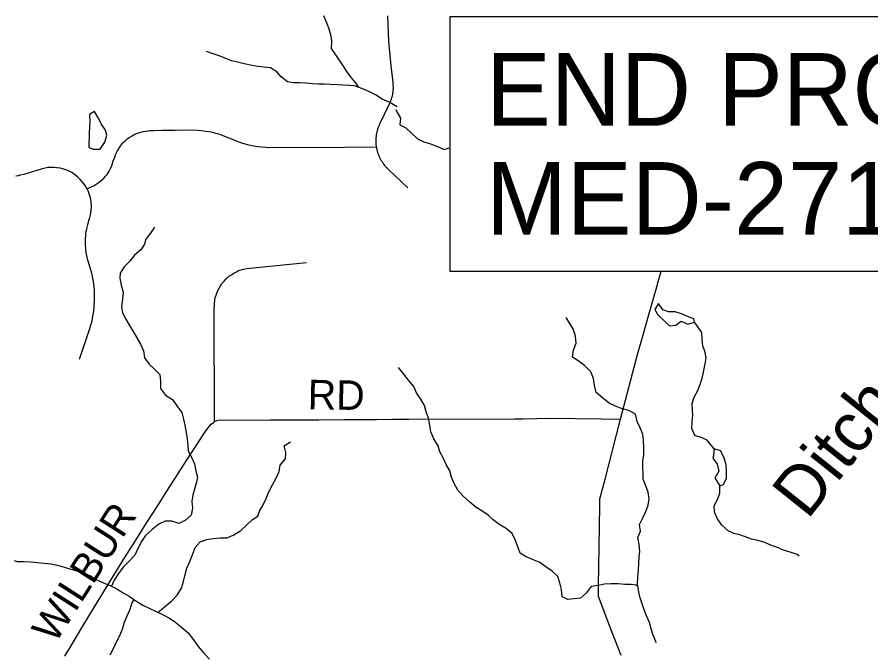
# Model space of a CAD drawing. Extents: x 0 to 34, y 0 to 22.
# Drawn here: x 5.327 to 6.974, y 16.805 to 18.033 of the extents above; entities that cross this region are included whole.
import ezdxf

# ---------------------------------------------------------------- set-up
doc = ezdxf.new("R2010")
doc.units = 0
for name, color, linetype in [('GM_X_County_Road', 7, 'Continuous'), ('GM_X_Minor_Lake', 7, 'Continuous'), ('GM_X_Minor_River', 7, 'Continuous'), ('GM_X_Minor_River_Text', 7, 'Continuous'), ('GM_X_Township_Road', 7, 'Continuous'), ('GM_X_Township_Road_Text', 7, 'Continuous'), ('SH_Text', 7, 'Continuous')]:
    doc.layers.add(name, color=color, linetype=linetype)

msp = doc.modelspace()

# ---------------------------------------------------------------- linework, layer by layer
at = {"layer": 'GM_X_County_Road'}
msp.add_lwpolyline([(6.4919, 16.8022), (6.4736, 16.8498), (6.448, 16.9162), (6.4482, 16.925), (6.4483, 16.9364), (6.4495, 17.0108), (6.4507, 17.0905), (6.451, 17.1044), (6.4603, 17.1399), (6.4907, 17.2575), (6.5234, 17.3825), (6.5342, 17.4204), (6.5433, 17.4522), (6.5524, 17.4842), (6.5619, 17.5175), (6.5622, 17.5188), (6.5692, 17.5433)], dxfattribs=at)
at = {"layer": 'GM_X_Minor_Lake'}
for points in [[(5.4854, 17.8353), (5.4831, 17.84), (5.4763, 17.8511), (5.4667, 17.8453), (5.4675, 17.8324), (5.4668, 17.8203), (5.466, 17.8088), (5.4653, 17.7815), (5.4742, 17.7784)], [(5.4854, 17.8353), (5.4831, 17.84), (5.4763, 17.8511), (5.4667, 17.8453), (5.4675, 17.8324), (5.4668, 17.8203), (5.466, 17.8088), (5.4653, 17.7815), (5.4741, 17.7785)], [(6.0573, 17.8544), (6.0592, 17.8503), (6.0664, 17.8377), (6.0653, 17.8252), (6.0767, 17.8191), (6.087, 17.81), (6.0992, 17.7978), (6.1114, 17.7925), (6.1243, 17.7884), (6.1377, 17.7831), (6.1506, 17.7774), (6.1601, 17.7808)], [(6.0573, 17.8544), (6.0592, 17.8503), (6.0664, 17.8377), (6.0653, 17.8252), (6.0767, 17.8191), (6.087, 17.81), (6.0992, 17.7978), (6.1114, 17.7925), (6.1243, 17.7884), (6.1377, 17.7831), (6.1506, 17.7774), (6.1601, 17.7808)], [(5.4741, 17.7784), (5.4874, 17.7781), (5.4965, 17.7918), (5.5003, 17.8055), (5.4976, 17.815), (5.4892, 17.8271), (5.4854, 17.8352)], [(5.4742, 17.7784), (5.4874, 17.7781), (5.4965, 17.7918), (5.5003, 17.8055), (5.4976, 17.815), (5.4892, 17.8271), (5.4854, 17.8353)], [(6.6332, 17.4445), (6.632, 17.4514), (6.6221, 17.4548), (6.6084, 17.4608), (6.5962, 17.465), (6.5833, 17.4646), (6.5723, 17.4684), (6.5639, 17.4806), (6.5567, 17.4691)], [(6.6332, 17.4445), (6.632, 17.4514), (6.6221, 17.4548), (6.6084, 17.4608), (6.5962, 17.465), (6.5833, 17.4646), (6.5723, 17.4684), (6.5639, 17.4806), (6.5567, 17.4691)], [(6.5567, 17.4691), (6.5628, 17.4589), (6.5742, 17.4482), (6.5849, 17.4376), (6.5974, 17.4388), (6.6077, 17.4464), (6.6202, 17.4411), (6.6332, 17.4445)], [(6.5567, 17.4691), (6.5628, 17.4589), (6.5742, 17.4482), (6.5849, 17.4376), (6.5974, 17.4388), (6.6077, 17.4464), (6.6202, 17.4411), (6.6332, 17.4445)], [(6.6819, 17.129), (6.6892, 17.132), (6.6953, 17.1442), (6.6952, 17.1579), (6.6945, 17.17), (6.6903, 17.1834), (6.6838, 17.197), (6.6716, 17.2004), (6.6701, 17.1871)], [(6.682, 17.129), (6.6892, 17.132), (6.6953, 17.1442), (6.6952, 17.1579), (6.6945, 17.17), (6.6903, 17.1834), (6.6838, 17.197), (6.6716, 17.2004), (6.6701, 17.1871)], [(6.6701, 17.1871), (6.669, 17.1826), (6.6773, 17.1708), (6.68, 17.1579), (6.6724, 17.1442), (6.6819, 17.129)], [(6.6701, 17.1871), (6.669, 17.1826), (6.6773, 17.1708), (6.68, 17.1579), (6.6724, 17.1442), (6.6819, 17.129)]]:
    msp.add_lwpolyline(points, dxfattribs=at)
at = {"layer": 'GM_X_Minor_River'}
for points in [[(5.9863, 17.8972), (5.9822, 17.9038), (5.9719, 17.9159), (5.9632, 17.9281), (5.9555, 17.9399), (5.9471, 17.9524), (5.9403, 17.9619), (5.9334, 17.9722), (5.9342, 17.9862), (5.933, 17.9961), (5.9288, 18.0098), (5.9242, 18.022), (5.9185, 18.0349)], [(6.0603, 17.8597), (6.0443, 17.8685), (6.0314, 17.8746), (6.0184, 17.8829), (6.0055, 17.8894), (5.9918, 17.8954), (5.978, 17.9), (5.9685, 17.9007), (5.9556, 17.9018), (5.9434, 17.9022), (5.9309, 17.9026), (5.9194, 17.9037), (5.9092, 17.9033), (5.8962, 17.9041), (5.8844, 17.9056), (5.8719, 17.9059), (5.8601, 17.9063), (5.8487, 17.9082), (5.8365, 17.9177), (5.8281, 17.9272), (5.8159, 17.9347), (5.8033, 17.9363), (5.7912, 17.9374), (5.7775, 17.94), (5.7649, 17.9427), (5.752, 17.9461), (5.7405, 17.9483), (5.7284, 17.9536), (5.7147, 17.9586), (5.7051, 17.962), (5.6926, 17.9662)], [(5.5923, 17.628), (5.5843, 17.6162), (5.5756, 17.6048), (5.5725, 17.5953), (5.5657, 17.5839), (5.5535, 17.574), (5.5448, 17.5626), (5.5338, 17.5511), (5.5262, 17.539), (5.5254, 17.5295), (5.5277, 17.5162), (5.532, 17.5029), (5.5304, 17.4892), (5.5282, 17.4755), (5.5305, 17.4629), (5.537, 17.4508), (5.5442, 17.4382), (5.5511, 17.4265), (5.5583, 17.4147), (5.5652, 17.4025), (5.5709, 17.3896), (5.5729, 17.3763), (5.5816, 17.3638), (5.5923, 17.3539), (5.6026, 17.3436), (5.6034, 17.3307), (5.6034, 17.317), (5.6133, 17.3041), (5.627, 17.2954), (5.6354, 17.2832), (5.6449, 17.2707), (5.648, 17.2581), (5.6503, 17.246), (5.653, 17.2323), (5.6553, 17.2194), (5.6561, 17.2064), (5.6568, 17.1969), (5.6633, 17.1844), (5.6694, 17.1715), (5.6717, 17.1585), (5.6748, 17.146), (5.6733, 17.1365), (5.6695, 17.1232), (5.6657, 17.1114), (5.6638, 17.0992), (5.6654, 17.0863), (5.6627, 17.073), (5.6517, 17.0631), (5.6395, 17.0566), (5.6254, 17.0611), (5.6125, 17.0615), (5.6003, 17.0554), (5.5874, 17.0451), (5.5749, 17.0337), (5.5669, 17.0223), (5.5608, 17.0097), (5.554, 16.996), (5.5441, 16.985), (5.532, 16.9724), (5.5229, 16.9602), (5.5145, 16.9477), (5.5091, 16.9359)], [(6.5596, 16.8267), (6.5587, 16.8292), (6.5534, 16.8417), (6.5496, 16.8535), (6.5465, 16.866), (6.5408, 16.879), (6.5362, 16.8904), (6.5324, 16.9018), (6.5282, 16.9151), (6.5251, 16.928), (6.5232, 16.9405), (6.5239, 16.9535), (6.5254, 16.9668), (6.5258, 16.9797), (6.5265, 16.993), (6.5277, 17.0025), (6.5269, 17.0162), (6.5238, 17.0295), (6.5295, 17.0417), (6.5272, 17.0546), (6.534, 17.0676), (6.5397, 17.0801), (6.5443, 17.0919), (6.5462, 17.1045), (6.5442, 17.1174), (6.5393, 17.1292), (6.5347, 17.1421), (6.5343, 17.152), (6.5339, 17.1645), (6.5339, 17.1767), (6.5354, 17.1896), (6.5354, 17.2029), (6.535, 17.2162), (6.5338, 17.2288), (6.5285, 17.241), (6.5227, 17.2535), (6.5197, 17.2672), (6.5067, 17.2744), (6.4942, 17.2778), (6.4808, 17.2831), (6.4687, 17.2888), (6.4568, 17.2983), (6.4439, 17.3093), (6.4404, 17.3226), (6.4389, 17.3363), (6.4332, 17.3488), (6.421, 17.361), (6.4092, 17.3701), (6.3978, 17.3773), (6.4, 17.3906), (6.4049, 17.4043), (6.4042, 17.418), (6.4, 17.4305), (6.386, 17.4535)], [(6.6715, 17.2004), (6.6579, 17.2175), (6.6464, 17.2225), (6.6343, 17.2266), (6.6282, 17.2396), (6.6289, 17.2525), (6.63, 17.2654), (6.6296, 17.2749), (6.6288, 17.2882), (6.6326, 17.3004), (6.6395, 17.313), (6.6448, 17.3267), (6.6486, 17.3396), (6.6516, 17.3518), (6.6538, 17.3643), (6.6557, 17.3761), (6.6534, 17.389), (6.6492, 17.3985), (6.6484, 17.4122), (6.6473, 17.4251), (6.6331, 17.4445)], [(6.5241, 16.9349), (6.5209, 16.9379), (6.5114, 16.9394), (6.4992, 16.9394), (6.4859, 16.9405), (6.4726, 16.9405), (6.4597, 16.9397), (6.4479, 16.9374), (6.4342, 16.9355), (6.4243, 16.9225), (6.4137, 16.913), (6.4015, 16.9115), (6.3889, 16.9103), (6.3783, 16.9156), (6.3771, 16.9293), (6.374, 16.9426), (6.3698, 16.9548), (6.3592, 16.9651), (6.347, 16.9734), (6.334, 16.9821), (6.3211, 16.9874), (6.3089, 16.9924), (6.2975, 16.9996), (6.2925, 17.0117), (6.2883, 17.0239), (6.2818, 17.0372), (6.2704, 17.0471), (6.2582, 17.0543), (6.2453, 17.0638), (6.2357, 17.0725), (6.2235, 17.0813), (6.2121, 17.0873), (6.1996, 17.0987), (6.1874, 17.1097), (6.1771, 17.1207), (6.1698, 17.134), (6.1649, 17.1462), (6.1614, 17.1584), (6.1545, 17.1705), (6.1496, 17.1819), (6.142, 17.1949), (6.1393, 17.2063), (6.1309, 17.2196), (6.1252, 17.2332), (6.1232, 17.2462), (6.1205, 17.2598), (6.116, 17.272), (6.1129, 17.2842), (6.1057, 17.2963), (6.0973, 17.3085), (6.0923, 17.3207), (6.082, 17.3328), (6.0729, 17.3446), (6.0626, 17.3571)], [(5.5989, 16.8853), (5.6021, 16.8881), (5.6143, 16.8984), (5.6257, 16.9075), (5.6359, 16.9189), (5.6439, 16.9322), (5.6481, 16.9448), (5.6511, 16.9585), (5.6545, 16.9707), (5.6602, 16.9836), (5.6651, 16.9965), (5.6708, 17.0102), (5.6803, 17.0213), (5.6932, 17.0258), (5.705, 17.0281), (5.7187, 17.0293), (5.7324, 17.0293), (5.745, 17.035), (5.7583, 17.0434), (5.7708, 17.0548), (5.7811, 17.0647), (5.7913, 17.0708), (5.7944, 17.0803), (5.8019, 17.0925), (5.8076, 17.1051), (5.8126, 17.118), (5.8194, 17.1313), (5.827, 17.1439), (5.8323, 17.1568), (5.8342, 17.1694), (5.8444, 17.1812), (5.8456, 17.1933), (5.8421, 17.2067), (5.8543, 17.2139)], [(6.8354, 16.9939), (6.8313, 16.9972), (6.8176, 17.0014), (6.805, 17.0055), (6.7932, 17.0105), (6.7818, 17.0146), (6.7689, 17.0199), (6.7563, 17.0241), (6.7434, 17.0268), (6.7301, 17.0317), (6.7205, 17.0351), (6.711, 17.0366), (6.6981, 17.0423), (6.6859, 17.0537), (6.6775, 17.0658), (6.6721, 17.0784), (6.671, 17.0909), (6.6774, 17.1031), (6.6824, 17.1153), (6.682, 17.129)], [(5.3216, 16.9855), (5.3276, 16.9836), (5.3398, 16.9836), (5.3528, 16.9828), (5.3657, 16.9813), (5.3794, 16.9802), (5.3923, 16.9791), (5.4053, 16.9761), (5.4178, 16.9726), (5.4308, 16.9689), (5.4426, 16.9658), (5.4555, 16.9613), (5.4685, 16.956), (5.481, 16.9484), (5.4936, 16.9423), (5.5069, 16.937), (5.5195, 16.9306), (5.5317, 16.923), (5.5435, 16.9165), (5.5564, 16.9074), (5.5698, 16.8991), (5.5819, 16.8934), (5.5953, 16.8869), (5.6086, 16.8809), (5.6208, 16.874), (5.633, 16.8661), (5.6448, 16.8562), (5.657, 16.8459), (5.6676, 16.8323), (5.6772, 16.8193), (5.6867, 16.8076), (5.6981, 16.795)], [(5.5524, 16.9102), (5.5484, 16.904), (5.5447, 16.891), (5.539, 16.8781), (5.5333, 16.8656), (5.5295, 16.8526), (5.5249, 16.8404), (5.5185, 16.8279), (5.5124, 16.8149), (5.506, 16.8032)]]:
    msp.add_lwpolyline(points, dxfattribs=at)
at = {"layer": 'GM_X_Township_Road'}
for points in [[(6.0809, 17.7038), (6.0441, 17.7382), (6.0424, 17.7398), (6.0414, 17.7408), (6.0405, 17.7417), (6.0396, 17.7427), (6.0387, 17.7436), (6.0378, 17.7446), (6.037, 17.7456), (6.0361, 17.7467), (6.0353, 17.7477), (6.0345, 17.7488), (6.0337, 17.7498), (6.0329, 17.7509), (6.0322, 17.752), (6.0315, 17.7531), (6.0308, 17.7542), (6.0301, 17.7554), (6.0294, 17.7565), (6.0288, 17.7576), (6.0281, 17.7588), (6.0275, 17.76), (6.0269, 17.7612), (6.0264, 17.7624), (6.0258, 17.7636), (6.0253, 17.7648), (6.0248, 17.766), (6.0243, 17.7672), (6.0238, 17.7685), (6.0234, 17.7697), (6.023, 17.771), (6.0226, 17.7723), (6.0222, 17.7735), (6.0219, 17.7748), (6.0215, 17.7761), (6.0212, 17.7774), (6.021, 17.7787), (6.0207, 17.78), (6.0205, 17.7813), (6.0202, 17.7826), (6.02, 17.7844), (6.0198, 17.7858), (6.0197, 17.7871), (6.0196, 17.7884), (6.0195, 17.7897), (6.0194, 17.791), (6.0195, 17.799), (6.0196, 17.8003), (6.0197, 17.8016), (6.0199, 17.8029), (6.02, 17.8042), (6.0202, 17.8056), (6.0204, 17.8069), (6.0206, 17.8082), (6.0209, 17.8095), (6.0212, 17.8108), (6.0215, 17.812), (6.0218, 17.8133), (6.0221, 17.8146), (6.0225, 17.8159), (6.0229, 17.8171), (6.0233, 17.8184), (6.0237, 17.8196), (6.0242, 17.8209), (6.0247, 17.8221), (6.0252, 17.8233), (6.0257, 17.8246), (6.0262, 17.8258), (6.0268, 17.827), (6.0454, 17.8658), (6.0461, 17.8674), (6.0467, 17.8686), (6.0472, 17.8698), (6.0477, 17.871), (6.0481, 17.8723), (6.0486, 17.8735), (6.049, 17.8748), (6.0494, 17.876), (6.0498, 17.8773), (6.0502, 17.8786), (6.0505, 17.8799), (6.0508, 17.8811), (6.0511, 17.8824), (6.0514, 17.8837), (6.0516, 17.885), (6.0518, 17.8863), (6.052, 17.8876), (6.0522, 17.889), (6.0524, 17.8903), (6.0525, 17.8916), (6.0526, 17.8929), (6.0527, 17.8942), (6.0525, 17.9048), (6.0524, 17.9061), (6.0523, 17.9074), (6.0485, 17.9391), (6.047, 17.9525), (6.0442, 17.9854), (6.0433, 18.0019), (6.0426, 18.0184), (6.0422, 18.0349)], [(5.4624, 17.7015), (5.4676, 17.7042), (5.4715, 17.7062), (5.4749, 17.7078), (5.478, 17.7095), (5.4854, 17.7145), (5.4902, 17.7184), (5.4946, 17.7225), (5.4977, 17.7259), (5.5006, 17.7293), (5.5048, 17.7359), (5.5075, 17.741), (5.5103, 17.7482), (5.512, 17.7535), (5.5153, 17.7625), (5.517, 17.767), (5.5187, 17.7713), (5.5203, 17.7744), (5.5218, 17.7772), (5.5243, 17.7811), (5.5271, 17.7851), (5.5291, 17.7879), (5.5313, 17.7904), (5.535, 17.7939), (5.5395, 17.7979), (5.5447, 17.8015), (5.5492, 17.8042), (5.5542, 17.8068), (5.5596, 17.8091), (5.5657, 17.811), (5.5705, 17.8121), (5.5753, 17.8131), (5.5795, 17.8137), (5.5838, 17.8141), (5.5902, 17.8144), (5.6071, 17.8146), (5.619, 17.8148), (5.6321, 17.815), (5.658, 17.8153), (5.6749, 17.815), (5.6824, 17.8144), (5.6915, 17.8131), (5.7015, 17.8113), (5.7077, 17.8097), (5.7155, 17.8075), (5.7259, 17.8038), (5.7334, 17.8009), (5.7406, 17.7978), (5.7494, 17.7942), (5.7558, 17.7919), (5.7618, 17.79), (5.7716, 17.7873), (5.7795, 17.7855), (5.7873, 17.784), (5.7918, 17.7834), (5.798, 17.7827), (5.8068, 17.782), (5.8142, 17.7816), (5.9583, 17.7822), (6.0202, 17.7826)], [(5.4477, 17.3737), (5.4657, 17.4267), (5.4676, 17.4327), (5.4696, 17.4397), (5.471, 17.4449), (5.4724, 17.451), (5.4735, 17.4572), (5.4743, 17.4626), (5.4749, 17.4673), (5.4755, 17.4731), (5.476, 17.4787), (5.4763, 17.4843), (5.4764, 17.4903), (5.4761, 17.5051), (5.4755, 17.5144), (5.4751, 17.5185), (5.4743, 17.5233), (5.4733, 17.5288), (5.4723, 17.5337), (5.4704, 17.5412), (5.4665, 17.5543), (5.4636, 17.5645), (5.4611, 17.5756), (5.46, 17.5826), (5.4595, 17.5875), (5.459, 17.5931), (5.4588, 17.5978), (5.459, 17.6073), (5.4594, 17.6107), (5.4597, 17.6141), (5.4605, 17.6192), (5.4614, 17.6243), (5.4622, 17.6277), (5.4635, 17.6332), (5.466, 17.6427), (5.4671, 17.6468), (5.4685, 17.6519), (5.4692, 17.6555), (5.4699, 17.6603), (5.4703, 17.6671), (5.4698, 17.6766), (5.4691, 17.681), (5.4685, 17.6841), (5.466, 17.6923), (5.464, 17.6979), (5.4624, 17.7015), (5.4606, 17.7045), (5.4589, 17.7073), (5.4531, 17.7149), (5.449, 17.7199), (5.4438, 17.7251), (5.4377, 17.7296), (5.4324, 17.7332), (5.4277, 17.7356), (5.4229, 17.7377), (5.417, 17.7397), (5.4105, 17.7414), (5.4035, 17.7425), (5.3984, 17.743), (5.3936, 17.7431), (5.39, 17.743), (5.3867, 17.7426), (5.3837, 17.7422), (5.3785, 17.7411), (5.3734, 17.7397), (5.3399, 17.7295), (5.3329, 17.7279), (5.3291, 17.7271), (5.3245, 17.7264)], [(5.708, 17.2532), (5.7072, 17.4672), (5.7076, 17.4805), (5.7083, 17.4863), (5.7093, 17.4915), (5.7114, 17.499), (5.7143, 17.5056), (5.7167, 17.5105), (5.7191, 17.5147), (5.722, 17.5191), (5.7262, 17.5241), (5.7296, 17.5276), (5.7349, 17.5325), (5.7403, 17.5363), (5.7449, 17.5391), (5.75, 17.542), (5.7533, 17.5435), (5.7569, 17.5448), (5.7614, 17.5462), (5.766, 17.5473), (5.7705, 17.5482), (5.776, 17.549), (5.8854, 17.56)], [(5.4192, 16.8012), (5.4237, 16.8085), (5.4275, 16.8146), (5.4444, 16.8429), (5.451, 16.8535), (5.4764, 16.8961), (5.5076, 16.9478), (5.5252, 16.9759), (5.5354, 16.9922), (5.5563, 17.0249), (5.5762, 17.0568), (5.5968, 17.0885), (5.6159, 17.1188), (5.6298, 17.141), (5.6422, 17.16), (5.662, 17.1911), (5.6683, 17.2006), (5.6884, 17.2313), (5.6927, 17.2377), (5.6956, 17.2414), (5.6977, 17.2438), (5.7015, 17.2482), (5.7058, 17.2516), (5.708, 17.2532), (5.7111, 17.2548), (5.7149, 17.256), (5.7198, 17.2565), (5.767, 17.2562), (5.8161, 17.2564), (5.8615, 17.2568), (5.9091, 17.2567), (5.9579, 17.2569), (5.9894, 17.257), (6.0199, 17.2572), (6.0513, 17.2576), (6.0828, 17.2579), (6.287, 17.2585), (6.3024, 17.2587), (6.3563, 17.2595), (6.4037, 17.2593), (6.4543, 17.2584), (6.4907, 17.2575)]]:
    msp.add_lwpolyline(points, dxfattribs=at)
at = {"layer": 'SH_Text'}
msp.add_lwpolyline([(6.1613, 17.5433), (7.8161, 17.5433), (7.8161, 18.0333), (6.1613, 18.0333)], close=True, dxfattribs=at)

# ---------------------------------------------------------------- texts
at = {"layer": 'GM_X_Minor_River_Text'}
msp.add_text('Ditch', height=0.09474, rotation=51.42, dxfattribs=at).set_placement((6.851, 17.0624))
at = {"layer": 'GM_X_Township_Road_Text'}
for s, rotation, p in [('RD', 359.0128, (5.8872, 17.2771)), ('WILBUR', 57.4216, (5.4005, 16.8234))]:
    msp.add_text(s, height=0.05682, rotation=rotation, dxfattribs=at).set_placement(p)
at = {"layer": 'SH_Text'}
for s, p in [('END PROJECT', (6.2313, 17.8233)), ('MED-271-6.58', (6.2313, 17.6133))]:
    msp.add_text(s, height=0.14, dxfattribs=at).set_placement(p)

doc.saveas('drawing.dxf')
